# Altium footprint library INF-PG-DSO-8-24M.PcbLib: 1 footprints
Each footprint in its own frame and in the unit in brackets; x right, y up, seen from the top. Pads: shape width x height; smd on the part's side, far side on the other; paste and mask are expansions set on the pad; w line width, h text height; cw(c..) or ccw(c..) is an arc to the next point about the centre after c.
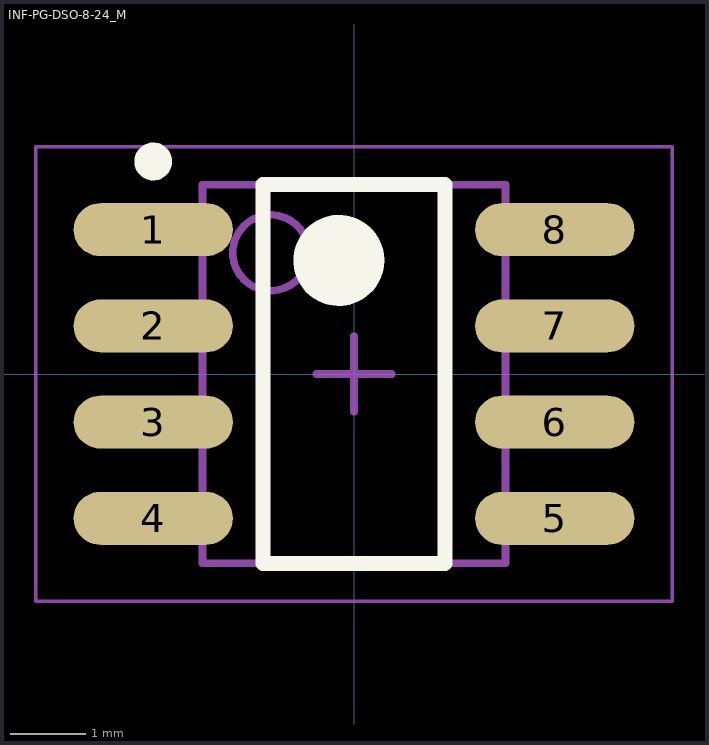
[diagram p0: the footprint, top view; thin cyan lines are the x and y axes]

## INF-PG-DSO-8-24_M [mm] "SOP, 8-Leads, Body 4.9x3.9mm, Pitch 1.27mm, IPC Low Density"
height 1.75
pads (8):
  oval 2.1x0.7 smd: 1(-2.65,1.905) 2(-2.65,0.635) 3(-2.65,-0.635) 4(-2.65,-1.905) 5(2.65,-1.905) 6(2.65,-0.635) 7(2.65,0.635) 8(2.65,1.905)
Top Overlay:
  circle w0.25: c-2.65,2.805 r0.125
  circle w0.6: c-0.2,1.5 r0.3
  lines w0.2: -1.2,-2.5 -1.2,2.5 1.2,2.5 1.2,-2.5 -1.2,-2.5
Mechanical 13:
  circle w0.1: c-1.1,1.6 r0.5
  lines w0.1: -2,-2.5 -2,2.5 2,2.5 2,-2.5 -2,-2.5
Mechanical 15:
  lines w0.05: -4.2,-3 -4.2,3 4.2,3 4.2,-3 -4.2,-3
  lines w0.1: -0.5,0 0.5,0 ; 0,-0.5 0,0.5
3D body: height 1.75, standoff 0.1, extent -2,-2.5 2,2.5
